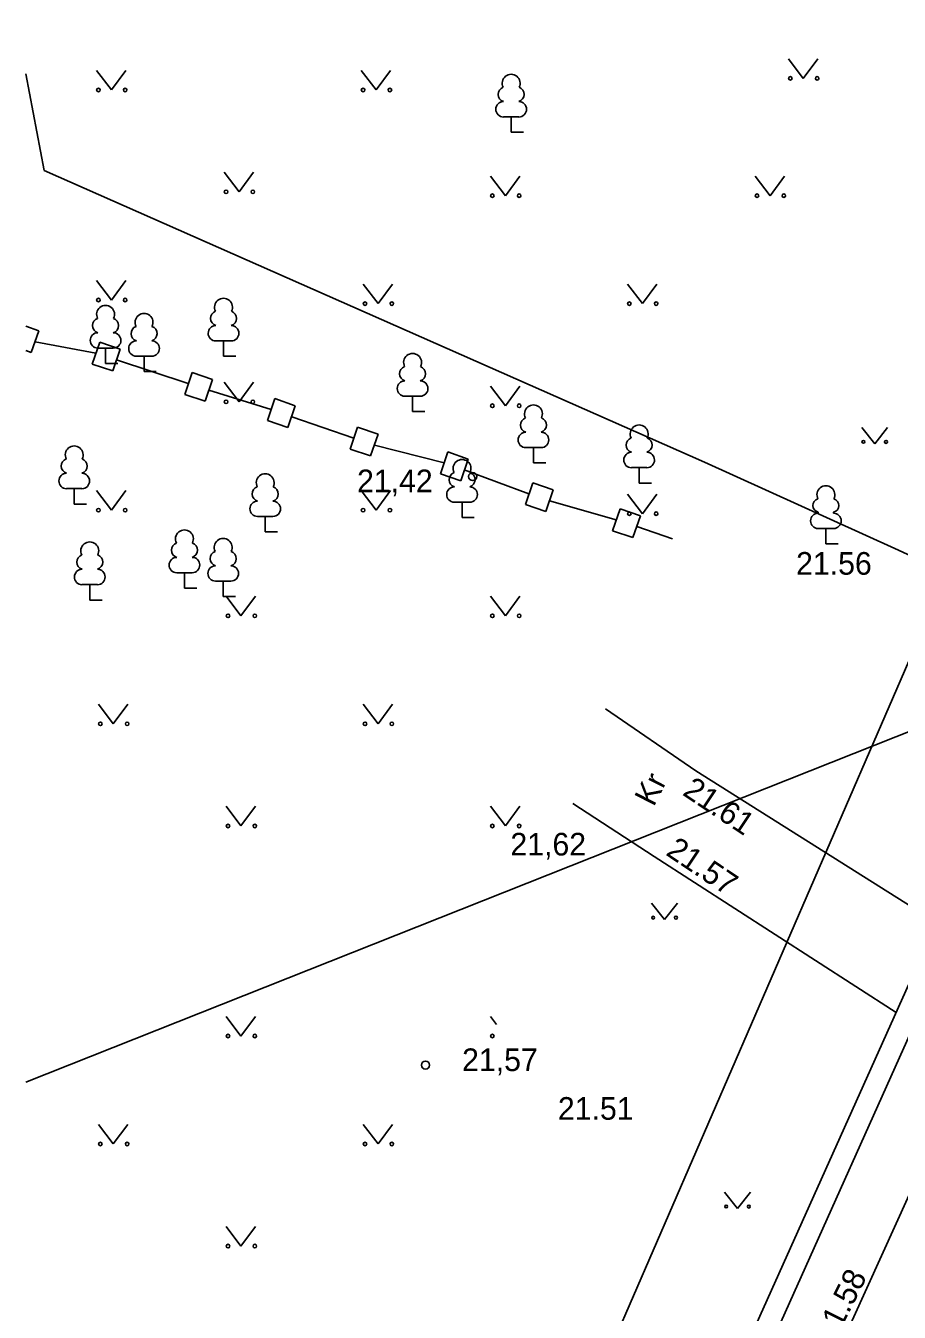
# Model space of a CAD drawing. Extents: x 714391 to 714584, y 6589993 to 6590151.
# Drawn here: x 714390.65 to 714417.68, y 6590052.39 to 6590092.2 of the extents above; entities that cross this region are included whole.
import ezdxf

# ---------------------------------------------------------------- set-up
doc = ezdxf.new("R2010")
doc.units = 0
for name, color, linetype in [('AED', 7, 'Continuous'), ('HALJASTUS', 7, 'Continuous'), ('KORGUS', 7, 'Continuous'), ('KPKAABEL', 7, 'Continuous'), ('KTRASS', 7, 'Continuous'), ('PUU', 7, 'Continuous'), ('SITRASS', 7, 'Continuous'), ('SKTRASS', 7, 'Continuous'), ('TEE', 7, 'Continuous'), ('По умолчанию', 7, 'Continuous')]:
    doc.layers.add(name, color=color, linetype=linetype)

msp = doc.modelspace()

# ---------------------------------------------------------------- linework, layer by layer
at = {"layer": 'AED'}
for points in [[(714391.05, 6590082.76), (714390.649, 6590082.9)], [(714390.82, 6590082.09), (714391.05, 6590082.76)], [(714392.82, 6590082.07), (714390.94, 6590082.42)], [(714392.94, 6590082.41), (714392.71, 6590081.73)], [(714393.57, 6590082.19), (714392.94, 6590082.41)], [(714390.649, 6590082.147), (714390.82, 6590082.09)], [(714393.34, 6590081.52), (714393.57, 6590082.19)], [(714395.68, 6590081.13), (714393.46, 6590081.86)], [(714392.71, 6590081.73), (714393.34, 6590081.52)], [(714395.8, 6590081.47), (714395.57, 6590080.79)], [(714396.43, 6590081.25), (714395.8, 6590081.47)], [(714396.2, 6590080.58), (714396.43, 6590081.25)], [(714395.57, 6590080.79), (714396.2, 6590080.58)], [(714398.24, 6590080.32), (714396.32, 6590080.92)], [(714398.36, 6590080.66), (714398.13, 6590079.98)], [(714398.99, 6590080.44), (714398.36, 6590080.66)], [(714398.76, 6590079.77), (714398.99, 6590080.44)], [(714398.13, 6590079.98), (714398.76, 6590079.77)], [(714400.8, 6590079.44), (714398.88, 6590080.1)], [(714400.92, 6590079.78), (714400.69, 6590079.1)], [(714401.55, 6590079.56), (714400.92, 6590079.78)], [(714401.32, 6590078.89), (714401.55, 6590079.56)], [(714400.69, 6590079.1), (714401.32, 6590078.89)], [(714403.6, 6590078.67), (714401.44, 6590079.22)], [(714403.71, 6590079.01), (714403.48, 6590078.33)], [(714404.34, 6590078.79), (714403.71, 6590079.01)], [(714404.11, 6590078.12), (714404.34, 6590078.79)], [(714403.48, 6590078.33), (714404.11, 6590078.12)], [(714406.22, 6590077.72), (714404.22, 6590078.46)], [(714406.34, 6590078.06), (714406.11, 6590077.38)], [(714406.97, 6590077.84), (714406.34, 6590078.06)], [(714406.74, 6590077.17), (714406.97, 6590077.84)], [(714408.92, 6590076.91), (714406.86, 6590077.5)], [(714406.11, 6590077.38), (714406.74, 6590077.17)], [(714409.04, 6590077.25), (714408.81, 6590076.57)], [(714409.67, 6590077.03), (714409.04, 6590077.25)], [(714409.44, 6590076.36), (714409.67, 6590077.03)], [(714410.667, 6590076.323), (714409.56, 6590076.7)], [(714408.81, 6590076.57), (714409.44, 6590076.36)]]:
    msp.add_lwpolyline(points, dxfattribs=at)
at = {"layer": 'HALJASTUS'}
for p, q in [((714414.247, 6590091.177), (714414.71, 6590090.57)), ((714414.71, 6590090.57), (714415.156, 6590091.177)), ((714392.837, 6590090.817), (714393.3, 6590090.21)), ((714393.3, 6590090.21), (714393.746, 6590090.817)), ((714401.027, 6590090.817), (714401.49, 6590090.21)), ((714401.49, 6590090.21), (714401.936, 6590090.817)), ((714396.787, 6590087.667), (714397.25, 6590087.06)), ((714397.25, 6590087.06), (714397.696, 6590087.667)), ((714405.027, 6590087.547), (714405.49, 6590086.94)), ((714405.49, 6590086.94), (714405.936, 6590087.547)), ((714413.217, 6590087.547), (714413.68, 6590086.94)), ((714413.68, 6590086.94), (714414.126, 6590087.547)), ((714392.837, 6590084.317), (714393.3, 6590083.71)), ((714393.3, 6590083.71), (714393.746, 6590084.317)), ((714401.087, 6590084.207), (714401.55, 6590083.6)), ((714401.55, 6590083.6), (714401.996, 6590084.207)), ((714409.267, 6590084.207), (714409.73, 6590083.6)), ((714409.73, 6590083.6), (714410.176, 6590084.207)), ((714396.787, 6590081.167), (714397.25, 6590080.56)), ((714397.25, 6590080.56), (714397.696, 6590081.167)), ((714405.027, 6590081.047), (714405.49, 6590080.44)), ((714405.49, 6590080.44), (714405.936, 6590081.047)), ((714416.517, 6590079.772), (714416.922, 6590079.267)), ((714416.922, 6590079.267), (714417.317, 6590079.772)), ((714392.837, 6590077.817), (714393.3, 6590077.21)), ((714393.3, 6590077.21), (714393.746, 6590077.817)), ((714401.027, 6590077.817), (714401.49, 6590077.21)), ((714401.49, 6590077.21), (714401.936, 6590077.817)), ((714409.267, 6590077.707), (714409.73, 6590077.1)), ((714409.73, 6590077.1), (714410.176, 6590077.707)), ((714396.847, 6590074.547), (714397.31, 6590073.94)), ((714397.31, 6590073.94), (714397.756, 6590074.547)), ((714405.027, 6590074.547), (714405.49, 6590073.94)), ((714405.49, 6590073.94), (714405.936, 6590074.547)), ((714392.897, 6590071.207), (714393.36, 6590070.6)), ((714393.36, 6590070.6), (714393.806, 6590071.207)), ((714401.087, 6590071.207), (714401.55, 6590070.6)), ((714401.55, 6590070.6), (714401.996, 6590071.207)), ((714396.847, 6590068.047), (714397.31, 6590067.44)), ((714397.31, 6590067.44), (714397.756, 6590068.047)), ((714405.027, 6590068.047), (714405.49, 6590067.44)), ((714405.49, 6590067.44), (714405.936, 6590068.047)), ((714410.015, 6590065.052), (714410.42, 6590064.547)), ((714410.42, 6590064.547), (714410.815, 6590065.052)), ((714396.847, 6590061.547), (714397.31, 6590060.94)), ((714397.31, 6590060.94), (714397.756, 6590061.547)), ((714392.897, 6590058.207), (714393.36, 6590057.6)), ((714393.36, 6590057.6), (714393.806, 6590058.207)), ((714401.087, 6590058.207), (714401.55, 6590057.6)), ((714401.55, 6590057.6), (714401.996, 6590058.207)), ((714412.272, 6590056.111), (714412.677, 6590055.606)), ((714412.677, 6590055.606), (714413.072, 6590056.111)), ((714396.847, 6590055.047), (714397.31, 6590054.44)), ((714397.31, 6590054.44), (714397.756, 6590055.047))]:
    msp.add_line(p, q, dxfattribs=at)
for centre, radius in [((714414.309, 6590090.57), 0.055), ((714415.138, 6590090.57), 0.055), ((714392.899, 6590090.21), 0.055), ((714393.728, 6590090.21), 0.055), ((714401.089, 6590090.21), 0.055), ((714401.918, 6590090.21), 0.055), ((714396.849, 6590087.06), 0.055), ((714397.678, 6590087.06), 0.055), ((714405.089, 6590086.94), 0.055), ((714405.918, 6590086.94), 0.055), ((714413.279, 6590086.94), 0.055), ((714414.108, 6590086.94), 0.055), ((714392.899, 6590083.71), 0.055), ((714393.728, 6590083.71), 0.055), ((714401.149, 6590083.6), 0.055), ((714401.978, 6590083.6), 0.055), ((714409.329, 6590083.6), 0.055), ((714410.158, 6590083.6), 0.055), ((714396.849, 6590080.56), 0.055), ((714397.678, 6590080.56), 0.055), ((714405.089, 6590080.44), 0.055), ((714405.918, 6590080.44), 0.055), ((714416.569, 6590079.322), 0.0428), ((714417.269, 6590079.322), 0.0452), ((714392.899, 6590077.21), 0.055), ((714393.728, 6590077.21), 0.055), ((714401.089, 6590077.21), 0.055), ((714401.918, 6590077.21), 0.055), ((714409.329, 6590077.1), 0.055), ((714410.158, 6590077.1), 0.055), ((714396.909, 6590073.94), 0.055), ((714397.738, 6590073.94), 0.055), ((714405.089, 6590073.94), 0.055), ((714405.918, 6590073.94), 0.055), ((714392.959, 6590070.6), 0.055), ((714393.788, 6590070.6), 0.055), ((714401.149, 6590070.6), 0.055), ((714401.978, 6590070.6), 0.055), ((714396.909, 6590067.44), 0.055), ((714397.738, 6590067.44), 0.055), ((714405.089, 6590067.44), 0.055), ((714405.918, 6590067.44), 0.055), ((714410.067, 6590064.602), 0.0428), ((714410.767, 6590064.602), 0.0452), ((714396.909, 6590060.94), 0.055), ((714397.738, 6590060.94), 0.055), ((714392.959, 6590057.6), 0.055), ((714393.788, 6590057.6), 0.055), ((714401.149, 6590057.6), 0.055), ((714401.978, 6590057.6), 0.055), ((714412.324, 6590055.662), 0.0428), ((714413.024, 6590055.662), 0.0452), ((714396.909, 6590054.44), 0.055), ((714397.738, 6590054.44), 0.055)]:
    msp.add_circle(centre, radius, dxfattribs=at)
at = {"layer": 'KORGUS'}
for centre in [(714404.48, 6590078.25), (714403.02, 6590060.04)]:
    msp.add_circle(centre, 0.125, dxfattribs=at)
at = {"layer": 'KPKAABEL'}
msp.add_lwpolyline([(714390.649, 6590090.709), (714391.22, 6590087.72), (714411.651, 6590078.699), (714417.543, 6590076.021), (714419.18, 6590075.27), (714445.64, 6590069.88), (714433.16, 6590042.04), (714420.76, 6590014.4), (714410.92, 6589992.711)], dxfattribs=at)
at = {"layer": 'KTRASS'}
msp.add_line((714409.68, 6590042.435), (714419.428, 6590064.172), dxfattribs=at)
at = {"layer": 'PUU'}
for p, q in [((714405.91, 6590089.375), (714405.43, 6590089.375)), ((714405.67, 6590088.9), (714405.67, 6590089.375)), ((714406.05, 6590088.9), (714405.67, 6590088.9)), ((714397.01, 6590082.445), (714396.53, 6590082.445)), ((714396.77, 6590081.97), (714396.77, 6590082.445)), ((714393.36, 6590082.225), (714392.88, 6590082.225)), ((714393.12, 6590081.75), (714393.12, 6590082.225)), ((714394.55, 6590081.975), (714394.07, 6590081.975)), ((714394.31, 6590081.5), (714394.31, 6590081.975)), ((714397.15, 6590081.97), (714396.77, 6590081.97)), ((714393.5, 6590081.75), (714393.12, 6590081.75)), ((714394.69, 6590081.5), (714394.31, 6590081.5)), ((714402.86, 6590080.735), (714402.38, 6590080.735)), ((714402.62, 6590080.26), (714402.62, 6590080.735)), ((714403, 6590080.26), (714402.62, 6590080.26)), ((714406.6, 6590079.145), (714406.12, 6590079.145)), ((714406.36, 6590078.67), (714406.36, 6590079.145)), ((714406.74, 6590078.67), (714406.36, 6590078.67)), ((714409.87, 6590078.525), (714409.39, 6590078.525)), ((714409.63, 6590078.05), (714409.63, 6590078.525)), ((714392.39, 6590077.875), (714391.91, 6590077.875)), ((714392.15, 6590077.4), (714392.15, 6590077.875)), ((714410.01, 6590078.05), (714409.63, 6590078.05)), ((714392.53, 6590077.4), (714392.15, 6590077.4)), ((714404.39, 6590077.455), (714403.91, 6590077.455)), ((714404.15, 6590076.98), (714404.15, 6590077.455)), ((714415.169, 6590077.146), (714415.169, 6590077.116)), ((714415.649, 6590077.146), (714415.649, 6590077.116)), ((714398.3, 6590077.015), (714397.82, 6590077.015)), ((714398.06, 6590076.54), (714398.06, 6590077.015)), ((714404.53, 6590076.98), (714404.15, 6590076.98)), ((714398.44, 6590076.54), (714398.06, 6590076.54)), ((714415.649, 6590076.641), (714415.169, 6590076.641)), ((714415.409, 6590076.166), (714415.409, 6590076.641)), ((714415.789, 6590076.166), (714415.409, 6590076.166)), ((714395.8, 6590075.275), (714395.32, 6590075.275)), ((714395.56, 6590074.8), (714395.56, 6590075.275)), ((714392.87, 6590074.905), (714392.39, 6590074.905)), ((714392.63, 6590074.43), (714392.63, 6590074.905)), ((714395.94, 6590074.8), (714395.56, 6590074.8)), ((714397, 6590075.015), (714396.52, 6590075.015)), ((714396.76, 6590074.54), (714396.76, 6590075.015)), ((714393.01, 6590074.43), (714392.63, 6590074.43)), ((714397.14, 6590074.54), (714396.76, 6590074.54))]:
    msp.add_line(p, q, dxfattribs=at)
for centre, radius, start, end in [((714405.67, 6590090.42), 0.277, 332.5799, 207.4201), ((714405.5, 6590090.073), 0.233, 109.0217, 253.1415), ((714405.84, 6590090.073), 0.233, 286.8508, 70.9859), ((714405.433, 6590089.612), 0.238, 90.0016, 269.3953), ((714405.907, 6590089.612), 0.238, 270.6047, 89.9984), ((714393.12, 6590083.27), 0.277, 332.5799, 207.4201), ((714396.77, 6590083.49), 0.277, 332.5799, 207.4201), ((714392.95, 6590082.923), 0.233, 109.0217, 253.1415), ((714393.29, 6590082.923), 0.233, 286.8508, 70.9859), ((714394.31, 6590083.02), 0.277, 332.5799, 207.4201), ((714396.6, 6590083.143), 0.233, 109.0217, 253.1415), ((714396.94, 6590083.143), 0.233, 286.8508, 70.9859), ((714392.883, 6590082.462), 0.238, 90.0016, 269.3953), ((714393.357, 6590082.462), 0.238, 270.6047, 89.9984), ((714394.14, 6590082.673), 0.233, 109.0217, 253.1415), ((714394.48, 6590082.673), 0.233, 286.8508, 70.9859), ((714396.533, 6590082.682), 0.238, 90.0016, 269.3953), ((714397.007, 6590082.682), 0.238, 270.6047, 89.9984), ((714394.073, 6590082.212), 0.238, 90.0016, 269.3953), ((714394.547, 6590082.212), 0.238, 270.6047, 89.9984), ((714402.62, 6590081.78), 0.277, 332.5799, 207.4201), ((714402.45, 6590081.433), 0.233, 109.0217, 253.1415), ((714402.79, 6590081.433), 0.233, 286.8508, 70.9859), ((714402.383, 6590080.972), 0.238, 90.0016, 269.3953), ((714402.857, 6590080.972), 0.238, 270.6047, 89.9984), ((714406.36, 6590080.19), 0.277, 332.5799, 207.4201), ((714406.19, 6590079.843), 0.233, 109.0217, 253.1415), ((714406.53, 6590079.843), 0.233, 286.8508, 70.9859), ((714406.123, 6590079.382), 0.238, 90.0016, 269.3953), ((714406.597, 6590079.382), 0.238, 270.6047, 89.9984), ((714409.63, 6590079.57), 0.277, 332.5799, 207.4201), ((714392.15, 6590078.92), 0.277, 332.5799, 207.4201), ((714409.46, 6590079.223), 0.233, 109.0217, 253.1415), ((714409.8, 6590079.223), 0.233, 286.8508, 70.9859), ((714391.98, 6590078.573), 0.233, 109.0217, 253.1415), ((714392.32, 6590078.573), 0.233, 286.8508, 70.9859), ((714404.15, 6590078.5), 0.277, 332.5799, 207.4201), ((714409.393, 6590078.762), 0.238, 90.0016, 269.3953), ((714409.867, 6590078.762), 0.238, 270.6047, 89.9984), ((714391.913, 6590078.112), 0.238, 90.0016, 269.3953), ((714392.387, 6590078.112), 0.238, 270.6047, 89.9984), ((714398.06, 6590078.06), 0.277, 332.5799, 207.4201), ((714403.98, 6590078.153), 0.233, 109.0217, 253.1415), ((714404.32, 6590078.153), 0.233, 286.8508, 70.9859), ((714397.89, 6590077.713), 0.233, 109.0217, 253.1415), ((714398.23, 6590077.713), 0.233, 286.8508, 70.9859), ((714403.913, 6590077.692), 0.238, 90.0016, 269.3953), ((714404.387, 6590077.692), 0.238, 270.6047, 89.9984), ((714415.409, 6590077.686), 0.277, 332.5799, 207.4201), ((714397.823, 6590077.252), 0.238, 90.0016, 269.3953), ((714398.297, 6590077.252), 0.238, 270.6047, 89.9984), ((714415.219, 6590077.354), 0.212, 105.2441, 257.079), ((714415.599, 6590077.354), 0.212, 282.921, 74.7559), ((714415.171, 6590076.879), 0.237, 90, 270), ((714415.646, 6590076.879), 0.237, 270, 90), ((714395.56, 6590076.32), 0.277, 332.5799, 207.4201), ((714396.76, 6590076.06), 0.277, 332.5799, 207.4201), ((714392.63, 6590075.95), 0.277, 332.5799, 207.4201), ((714395.39, 6590075.973), 0.233, 109.0217, 253.1415), ((714395.73, 6590075.973), 0.233, 286.8508, 70.9859), ((714396.59, 6590075.713), 0.233, 109.0217, 253.1415), ((714396.93, 6590075.713), 0.233, 286.8508, 70.9859), ((714392.46, 6590075.603), 0.233, 109.0217, 253.1415), ((714392.8, 6590075.603), 0.233, 286.8508, 70.9859), ((714395.323, 6590075.512), 0.238, 90.0016, 269.3953), ((714395.797, 6590075.512), 0.238, 270.6047, 89.9984), ((714396.523, 6590075.252), 0.238, 90.0016, 269.3953), ((714396.997, 6590075.252), 0.238, 270.6047, 89.9984), ((714392.393, 6590075.142), 0.238, 90.0016, 269.3953), ((714392.867, 6590075.142), 0.238, 270.6047, 89.9984)]:
    msp.add_arc(centre, radius, start, end, dxfattribs=at)
at = {"layer": 'SITRASS'}
msp.add_line((714428.828, 6590097.575), (714403.181, 6590038.435), dxfattribs=at)
at = {"layer": 'SKTRASS'}
msp.add_lwpolyline([(714434.439, 6590076.889), (714390.649, 6590059.517)], dxfattribs=at)
at = {"layer": 'TEE'}
for points in [[(714390.65, 6590124.59), (714396, 6590120.47), (714402.53, 6590115.27), (714412.65, 6590108.38), (714428.405, 6590098.635), (714430.062, 6590097.596), (714432.277, 6590096.218), (714432.498, 6590094.946), (714428.283, 6590085.404), (714423.452, 6590074.702), (714420.733, 6590068.851), (714418.831, 6590064.457), (714408.849, 6590042.202), (714401.401, 6590025.886)], [(714408.586, 6590071.058), (714411.386, 6590069.149), (714418.831, 6590064.457)], [(714407.575, 6590068.129), (714410.094, 6590066.498), (714417.582, 6590061.672)], [(714403.962, 6590024.844), (714405.48, 6590028.39), (714415.772, 6590051.14), (714422.922, 6590066.912)]]:
    msp.add_lwpolyline(points, dxfattribs=at)
at = {"layer": 'По умолчанию'}
msp.add_line((714405.027, 6590061.547), (714405.219, 6590061.295), dxfattribs=at)
msp.add_circle((714405.089, 6590060.94), 0.055, dxfattribs=at)

# ---------------------------------------------------------------- texts
at = {"layer": 'KORGUS'}
for s, p in [('21,42', (714400.901, 6590077.765)), ('21.56', (714414.486, 6590075.213)), ('21,62', (714405.646, 6590066.525)), ('21,57', (714404.151, 6590059.855)), ('21.51', (714407.116, 6590058.349))]:
    msp.add_text(s, height=0.7, dxfattribs=at).set_placement(p)
for s, rotation, p in [('21.61', 326.3099, (714410.94, 6590068.418)), ('21.57', 326.1173, (714410.424, 6590066.561)), ('21.58', 63.4349, (714415.645, 6590051.403))]:
    msp.add_text(s, height=0.7, rotation=rotation, dxfattribs=at).set_placement(p)
at = {"layer": 'TEE'}
msp.add_text('Kr', height=0.7, rotation=62.8402, dxfattribs=at).set_placement((714410.08, 6590068.01))

doc.saveas('drawing.dxf')
